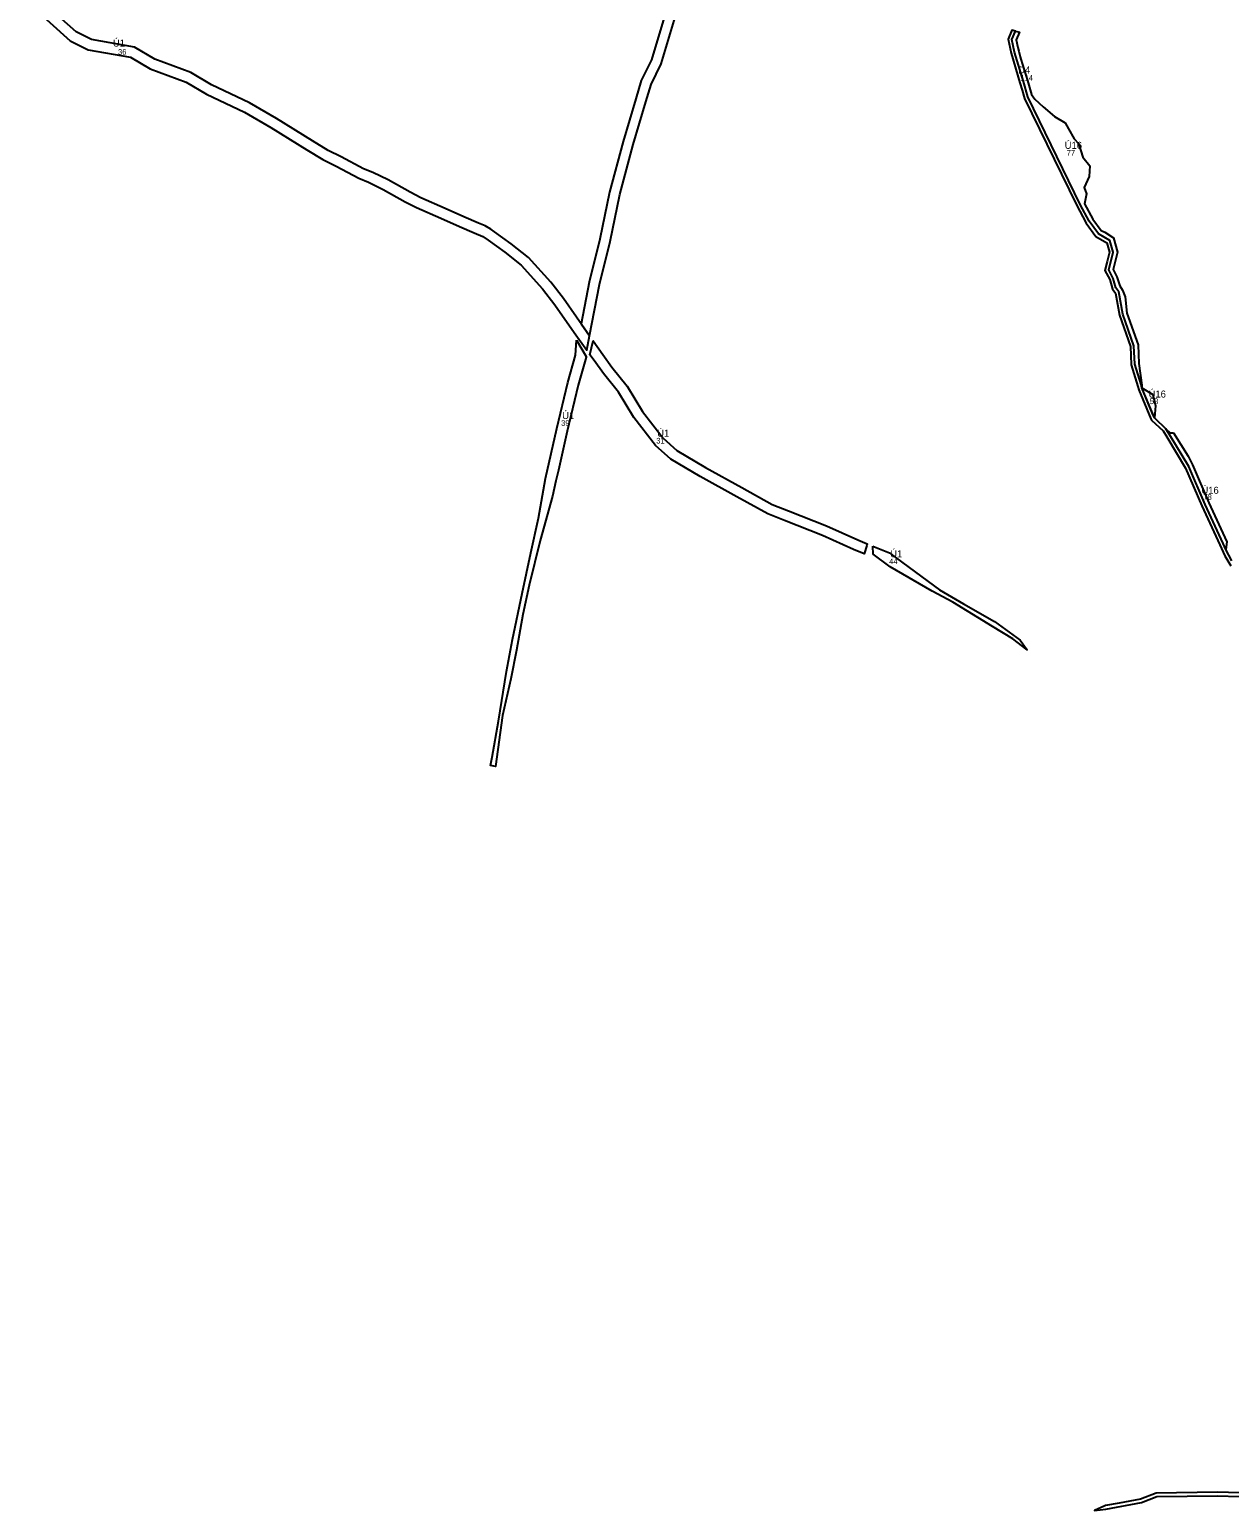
# Model space of a CAD drawing. Extents: x -521621 to -516857, y -1190025 to -1185894.
# Drawn here: x -521169 to -519468, y -1190025 to -1187926 of the extents above; entities that cross this region are included whole.
import ezdxf

# ---------------------------------------------------------------- set-up
doc = ezdxf.new("R2010")
doc.units = 0
for name, color, linetype in [('VPO_id', 7, 'Continuous'), ('VPO_n', 7, 'Continuous'), ('VPS_id', 7, 'Continuous'), ('VPS_n', 7, 'Continuous')]:
    doc.layers.add(name, color=color, linetype=linetype)

msp = doc.modelspace()

# ---------------------------------------------------------------- linework, layer by layer
at = {"layer": 'VPO_n'}
for points in [[(-521168.6, -1187890.1), (-521111, -1187941.7), (-521085.6, -1187954.5), (-521025.4, -1187965.1), (-520997.5, -1187981.5), (-520946.7, -1188000.3), (-520917.8, -1188017.4), (-520863.8, -1188042.8), (-520826.5, -1188064.8), (-520775.5, -1188096.2), (-520752.8, -1188110.2), (-520733.9, -1188119.6), (-520701.8, -1188136.6), (-520688.3, -1188142.3), (-520667.4, -1188152.3), (-520636.3, -1188169.8), (-520620.3, -1188177.8), (-520585.4, -1188193.1), (-520559, -1188204.8), (-520538.2, -1188214.1), (-520526.1, -1188219), (-520518.5, -1188224.5), (-520495.1, -1188241.2), (-520471.8, -1188259.7), (-520441.4, -1188293.5), (-520423.8, -1188315.9), (-520396.5, -1188355.1), (-520378.7, -1188380.4), (-520374.8, -1188360.1), (-520411.8, -1188307), (-520429.9, -1188283.9), (-520461.5, -1188248.8), (-520486.1, -1188229.3), (-520509.7, -1188212.3), (-520514.6, -1188208.8), (-520522.7, -1188204.2), (-520532.3, -1188200.3), (-520552.9, -1188191.1), (-520579.3, -1188179.4), (-520613.9, -1188164.2), (-520629.3, -1188156.5), (-520660.4, -1188139), (-520682.2, -1188128.6), (-520695.3, -1188123), (-520727, -1188106.3), (-520745.5, -1188097.1), (-520767.7, -1188083.4), (-520818.7, -1188052), (-520856.8, -1188029.5), (-520910.8, -1188004.2), (-520940.2, -1187986.7), (-520991, -1187967.9), (-521020.1, -1187950.8), (-521080.8, -1187940.1), (-521102.5, -1187929.2), (-521159.7, -1187878)], [(-520264.9, -1187894.4), (-520287.1, -1187968.9), (-520301.6, -1187998.2), (-520309.3, -1188024.2), (-520327.3, -1188084.5), (-520346.3, -1188156.2), (-520360.4, -1188222.9), (-520375.2, -1188283.8)], [(-520375.2, -1188283.8), (-520386.7, -1188343), (-520374.8, -1188360.1), (-520360.6, -1188287), (-520345.7, -1188226.2), (-520331.7, -1188159.7), (-520312.9, -1188088.6), (-520295, -1188028.5), (-520287.6, -1188003.7), (-520273.1, -1187974.4), (-520250.5, -1187898.7)], [(-519753.6, -1188021), (-519759.8, -1187999.7), (-519772.2, -1187957.8), (-519776.4, -1187939.9), (-519771.1, -1187928.1), (-519765.3, -1187929.6), (-519770.1, -1187940.5), (-519767.8, -1187951.4), (-519766.4, -1187956.3), (-519764.2, -1187964.5), (-519763.4, -1187967.8), (-519754.1, -1187998.1), (-519748.2, -1188018), (-519743.4, -1188024.4), (-519731.6, -1188035.5), (-519715.8, -1188049.2), (-519700.7, -1188058.2), (-519695.7, -1188066.7), (-519687.8, -1188080.9), (-519681.8, -1188087.4), (-519675.7, -1188106.7), (-519665.5, -1188119.1), (-519666.7, -1188133.9), (-519673.5, -1188149.5), (-519670.1, -1188158.8), (-519673.1, -1188172.7), (-519661.3, -1188194.4), (-519649.4, -1188210.8), (-519644.1, -1188212.8), (-519632.2, -1188220.8), (-519626.4, -1188241.3), (-519632.4, -1188265.8), (-519627.1, -1188276.2), (-519623.3, -1188289), (-519619.1, -1188295), (-519615.4, -1188304.7), (-519613, -1188327.8), (-519597.1, -1188372.8), (-519596.1, -1188399.1), (-519592.1, -1188429.9), (-519591.7, -1188433.7), (-519593, -1188429.1), (-519602, -1188400.1), (-519603, -1188373.9), (-519618.8, -1188329.3), (-519624.7, -1188297.4), (-519628.8, -1188291.7), (-519632.7, -1188278.5), (-519638.8, -1188266.5), (-519632.6, -1188241.5), (-519637.4, -1188224.8), (-519653.5, -1188215.3), (-519666.4, -1188197.6), (-519679.4, -1188173.7)], [(-519679.4, -1188173.7), (-519753.6, -1188021)]]:
    msp.add_lwpolyline(points, dxfattribs=at)
for points in [[(-520393.3, -1188366.1), (-520379.5, -1188389.1), (-520379.8, -1188390), (-520390.9, -1188429.8), (-520406.4, -1188494.8), (-520419, -1188550.3), (-520422.5, -1188565.2), (-520427.5, -1188587.1), (-520444.8, -1188650.2), (-520460.4, -1188713.3), (-520469.2, -1188755), (-520478.3, -1188805.3), (-520486.3, -1188845.9), (-520498.2, -1188898), (-520507.9, -1188970.2), (-520515.2, -1188968.8), (-520512.9, -1188957), (-520503.7, -1188906.2), (-520492.7, -1188835.4), (-520484, -1188790.1), (-520470.4, -1188724.9), (-520458.1, -1188667.6), (-520447, -1188618.5), (-520437.2, -1188562.2), (-520421, -1188491.4), (-520405.4, -1188426), (-520394.5, -1188387.2)], [(-520374.2, -1188386.8), (-520369.9, -1188366.8), (-520356.2, -1188386.2), (-520343, -1188404.4), (-520321.7, -1188431.3), (-520299.7, -1188467.3), (-520270.4, -1188505), (-520250.9, -1188522.4), (-520210.3, -1188546.3), (-520159, -1188575), (-520115.9, -1188598.8), (-520093, -1188607.8), (-520039, -1188629.1), (-519994.6, -1188649.1), (-519981.1, -1188654.6), (-519981.5, -1188657.1), (-519985.5, -1188669), (-520000.5, -1188662.8), (-520044.8, -1188642.9), (-520098.5, -1188621.8), (-520122.3, -1188612.4), (-520166.2, -1188588.2), (-520217.8, -1188559.3), (-520259.8, -1188534.6), (-520281.4, -1188515.3), (-520312.1, -1188475.8), (-520334, -1188439.9), (-520355, -1188413.5), (-520368.4, -1188394.9)], [(-519591.7, -1188433.7), (-519576.2, -1188443), (-519572.3, -1188459.2), (-519574.1, -1188476.3)], [(-519547.1, -1188497.4), (-519526.3, -1188530.5), (-519519.9, -1188542.5), (-519496.8, -1188596.4), (-519471.2, -1188651.7), (-519472.8, -1188662.7), (-519476.6, -1188654.1), (-519502.3, -1188598.8), (-519525.3, -1188545.3), (-519552.2, -1188500.6), (-519558, -1188491.5), (-519551.5, -1188497.5)], [(-519973.3, -1188657.8), (-519949.6, -1188667.6), (-519939.6, -1188675), (-519878.5, -1188719.9), (-519844.6, -1188739.5), (-519800.6, -1188764.7), (-519764.4, -1188791), (-519754.2, -1188804.9), (-519774.7, -1188789.1), (-519803.5, -1188771.9), (-519859.7, -1188737.4), (-519889, -1188721.9), (-519948.5, -1188687.1), (-519972.8, -1188669.2)]]:
    msp.add_lwpolyline(points, close=True, dxfattribs=at)
at = {"layer": 'VPS_n'}
for points in [[(-519464.3, -1188678.6), (-519472.8, -1188662.7), (-519476.6, -1188654.1), (-519502.3, -1188598.8), (-519525.3, -1188545.3), (-519552.2, -1188500.6), (-519558, -1188491.5), (-519572.6, -1188477.7), (-519574.1, -1188476.3), (-519577.1, -1188468.9), (-519591.7, -1188433.7), (-519593, -1188429.1), (-519602, -1188400.1), (-519603, -1188373.9), (-519618.8, -1188329.3), (-519624.7, -1188297.4), (-519628.8, -1188291.7), (-519632.7, -1188278.5), (-519638.8, -1188266.5), (-519632.6, -1188241.5), (-519637.4, -1188224.8), (-519653.5, -1188215.3), (-519666.4, -1188197.6), (-519679.4, -1188173.7), (-519753.6, -1188021), (-519759.8, -1187999.7), (-519772.2, -1187957.8), (-519776.4, -1187939.9), (-519771.1, -1187928.1), (-519776, -1187926.9), (-519781.6, -1187939.4), (-519777.1, -1187959.1), (-519764.6, -1188001.2), (-519761.6, -1188011.6), (-519758, -1188023.6), (-519684.7, -1188174.4), (-519670.6, -1188200.3), (-519656.9, -1188219.1), (-519641.6, -1188228.1), (-519637.8, -1188241.5), (-519641, -1188254.7), (-519644.1, -1188267.2), (-519637.3, -1188280.3), (-519633.3, -1188293.9), (-519631.6, -1188296.3), (-519629.4, -1188299.4), (-519623.6, -1188330.6), (-519608, -1188374.8), (-519607.5, -1188387.9), (-519607, -1188400.9), (-519597.4, -1188431.8), (-519595.9, -1188436.5), (-519579.2, -1188477.4), (-519578, -1188479.5), (-519561.8, -1188494.7), (-519556.5, -1188503.2), (-519529.8, -1188547.6), (-519506.8, -1188600.9), (-519481.2, -1188656.2), (-519474.1, -1188671.9), (-519465.9, -1188685.9)], [(-519422.8, -1190000.8), (-519484.8, -1189998.9), (-519571.6, -1190000), (-519593.6, -1190008.4), (-519624, -1190014.1), (-519643.6, -1190017.8), (-519644.5, -1190017.9), (-519658.8, -1190024.5), (-519642.9, -1190022.7), (-519592.2, -1190013.2), (-519570.6, -1190005), (-519484.8, -1190003.9), (-519423, -1190005.8)]]:
    msp.add_lwpolyline(points, dxfattribs=at)

# ---------------------------------------------------------------- texts
at = {"layer": 'VPO_id'}
for s, p in [('36', (-521043.2, -1187961.6)), ('77', (-519698.3, -1188104.4)), ('58', (-519580.5, -1188456.7)), ('39', (-520415.1, -1188487.5)), ('31', (-520280.3, -1188512.5)), ('78', (-519504.6, -1188592.3)), ('44', (-519950, -1188683.5))]:
    msp.add_text(s, height=8, dxfattribs=at).set_placement(p)
at = {"layer": 'VPO_n'}
for s, p in [('Ú1', (-521050.5, -1187950)), ('Ú16', (-519701.2, -1188094.9)), ('Ú16', (-519582.3, -1188447.4)), ('Ú1', (-520413.6, -1188477.8)), ('Ú1', (-520278.9, -1188502.9)), ('Ú16', (-519507.4, -1188583.8)), ('Ú1', (-519948.6, -1188673.9))]:
    msp.add_text(s, height=10, dxfattribs=at).set_placement(p)
at = {"layer": 'VPS_id'}
msp.add_text('114', height=8, dxfattribs=at).set_placement((-519764, -1187998.2))
at = {"layer": 'VPS_n'}
msp.add_text('D4', height=10, dxfattribs=at).set_placement((-519767.3, -1187988.2))

doc.saveas('drawing.dxf')
